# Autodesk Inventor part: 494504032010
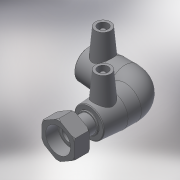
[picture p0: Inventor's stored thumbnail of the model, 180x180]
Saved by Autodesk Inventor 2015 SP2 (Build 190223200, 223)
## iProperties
Created: 2017-06
Part Number: 494504032010
Material: Generic
Description: PLASSON 90° ELBOW FEMALE FREE NUT TRANSITION 32-1"
Document SubType Name: Modeling
Designer: KIM
Mass: 55.0731 g
Surface Area: 148.067 cm^2
Volume: 55.0731 cm^3
Density: 1 g/cm^3
Appearance: Default
Author: KIM
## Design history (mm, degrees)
derived "494504.ipt"
feature "Solid1::494504.ipt"
tag "TaggingFeature1"
body "Solid1"
other parameters: "d2" = 44, "d4" = 27.66667, "d5" = 39.6, "d8" = 168 deg, "d10" = 16, "d11" = 5.33333, "d29" = 43, "d30" = 15, "d31" = 45.65, "d34" = 5 deg, "d41" = 4, "d42" = 14, "d43" = 0, "d48" = 61, "d49" = 32, "d50" = 27.2, "d51" = 16, "d54" = 90 deg, "d57" = 32, "d59" = 0, "d61" = 90 deg, "d86" = 3, "d87" = 0, "d97" = 19, "d98" = 36, "d99" = 45.4365, "d109" = 0.96, "d116" = 18, "d117" = 30.291, "d118" = 14.4, "d119" = 1.44, "d120" = 24.2328, "d121" = 1.44, "d122" = 21.2037, "d123" = 19, "d124" = 1.51455, "d128" = 0, "d_" = 32, "L_" = 119, "D_" = 19, "A_" = 43, "d_2" = 12, "L_2" = 36, "D_1" = 44, "G_" = 30.291
